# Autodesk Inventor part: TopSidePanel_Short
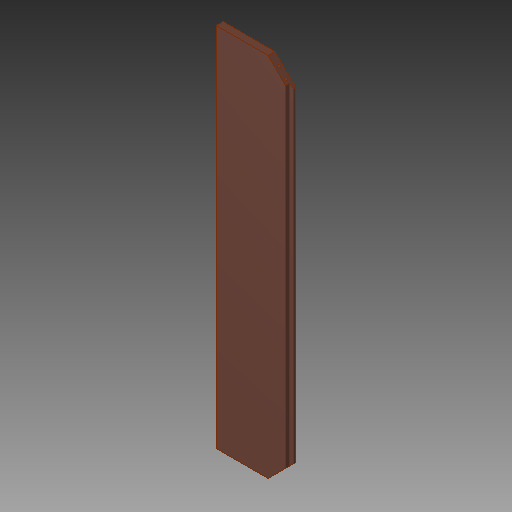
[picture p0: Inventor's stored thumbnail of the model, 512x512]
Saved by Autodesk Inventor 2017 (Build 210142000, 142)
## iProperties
Created: 2017-05
Part Number: TopSidePanel_Short
Material: Generic
Document SubType Name: Modeling
Designer: Savy
Density: 1 g/cm^3
Appearance: Default
Author: Savy
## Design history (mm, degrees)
feature "SOLID1"
body "Solid1"
